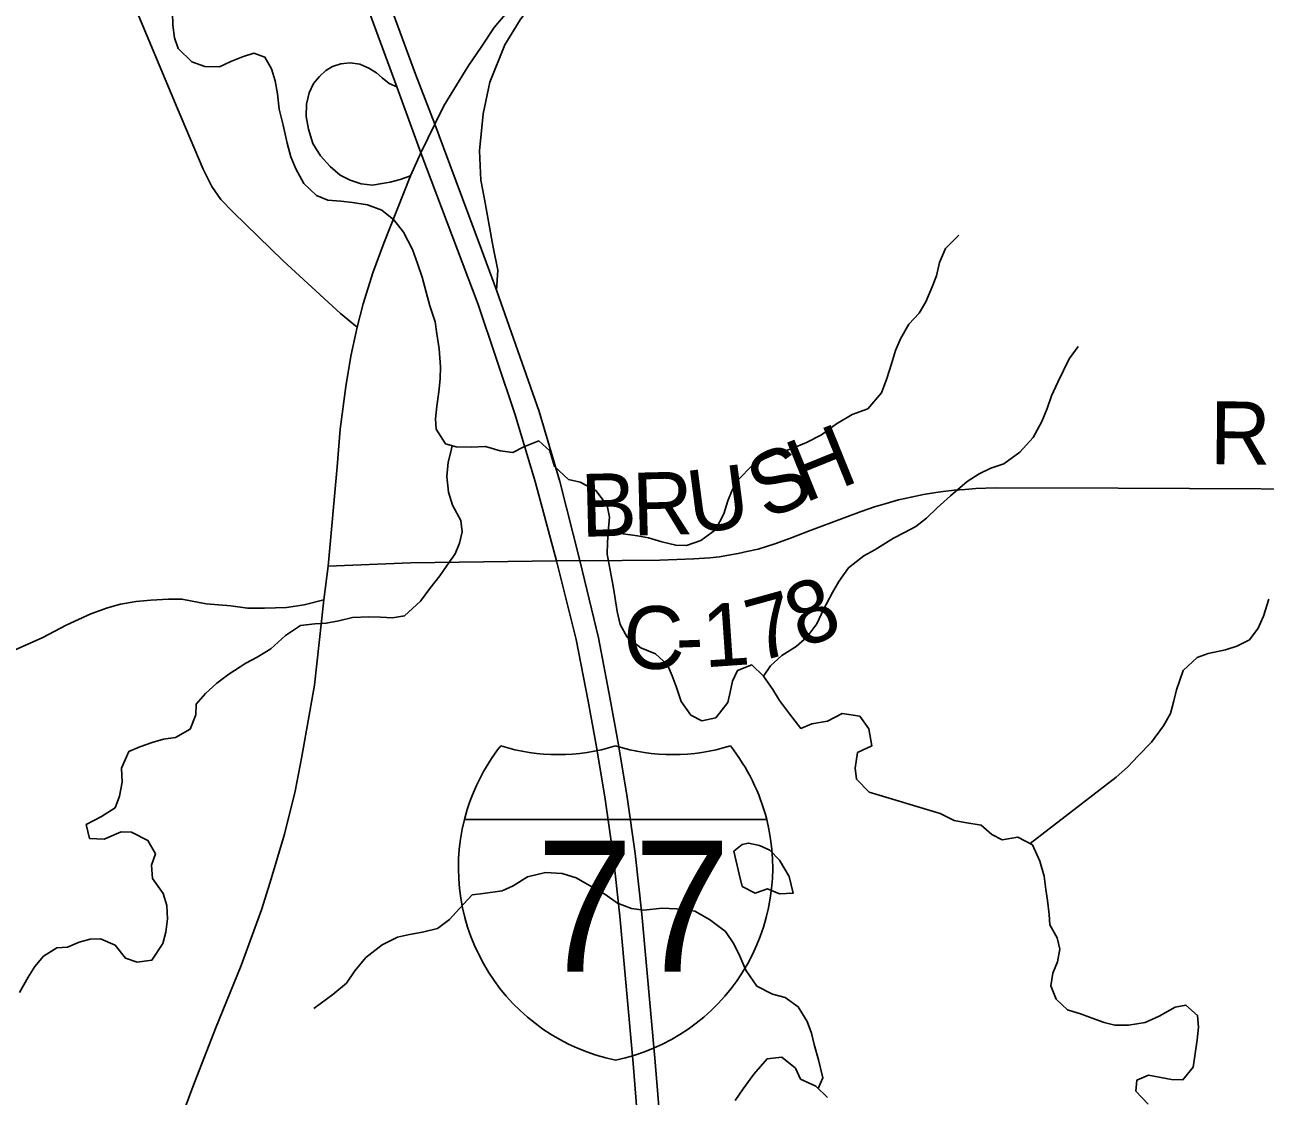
# Model space of a CAD drawing. Extents: x 0 to 34, y 0 to 22.
# Drawn here: x 5.653 to 6.774, y 18.908 to 19.877 of the extents above; entities that cross this region are included whole.
import ezdxf

# ---------------------------------------------------------------- set-up
doc = ezdxf.new("R2010")
doc.units = 0
for name, color, linetype in [('GM_X_City_Street', 7, 'Continuous'), ('GM_X_County_Road', 7, 'Continuous'), ('GM_X_County_Road_Text', 7, 'Continuous'), ('GM_X_Interstate_Location', 7, 'Continuous'), ('GM_X_Interstate_Route', 7, 'Continuous'), ('GM_X_Interstate_Shield', 7, 'Continuous'), ('GM_X_Minor_Lake', 7, 'Continuous'), ('GM_X_Minor_River', 7, 'Continuous'), ('GM_X_State_Route', 7, 'Continuous')]:
    doc.layers.add(name, color=color, linetype=linetype)

msp = doc.modelspace()

# ---------------------------------------------------------------- linework, layer by layer
at = {"layer": 'GM_X_City_Street'}
msp.add_line((5.9271, 19.3876), (6.0016, 19.3906), dxfattribs=at)
msp.add_lwpolyline([(5.644, 19.3118), (5.6691, 19.3231), (5.6903, 19.334), (5.7126, 19.3443), (5.7276, 19.3499), (5.7393, 19.3531), (5.7534, 19.3556), (5.7668, 19.3568), (5.7827, 19.3577), (5.7949, 19.3577), (5.8167, 19.3535), (5.8391, 19.3515), (5.8541, 19.3496), (5.8695, 19.3496), (5.8893, 19.3501), (5.9054, 19.3526), (5.9232, 19.357)], dxfattribs=at)
at = {"layer": 'GM_X_County_Road'}
for points in [[(5.9534, 19.6037), (5.9382, 19.6159), (5.8865, 19.6636), (5.8412, 19.7076), (5.8301, 19.7191), (5.822, 19.7309), (5.814, 19.7466), (5.7907, 19.8021), (5.7419, 19.9191), (5.7283, 19.9573), (5.7195, 19.9843), (5.7082, 20.0221)], [(5.7891, 18.8744), (5.8046, 18.9165), (5.8253, 18.9692), (5.8485, 19.0262), (5.8667, 19.0766), (5.8746, 19.1017), (5.8875, 19.1451), (5.8974, 19.184), (5.9034, 19.2153), (5.9148, 19.2798), (5.9232, 19.357), (5.9271, 19.3876), (5.9354, 19.4774), (5.9379, 19.5114), (5.943, 19.55), (5.9476, 19.5775), (5.9534, 19.6037), (5.9589, 19.6249), (5.9674, 19.6528), (5.9775, 19.6797), (6.0017, 19.7406)], [(6.159, 19.3924), (6.2269, 19.393), (6.2579, 19.3942), (6.2722, 19.3951), (6.2809, 19.3959), (6.2891, 19.3973), (6.2978, 19.3988), (6.3058, 19.4007), (6.316, 19.4029), (6.331, 19.4076), (6.3451, 19.4128), (6.3615, 19.419), (6.3936, 19.4311), (6.4092, 19.4368), (6.4212, 19.4412), (6.4317, 19.4441), (6.443, 19.4474), (6.4542, 19.45), (6.4655, 19.4524), (6.4765, 19.4541), (6.4834, 19.4551), (6.4933, 19.4561), (6.5031, 19.4569), (6.5128, 19.4577), (6.5305, 19.4583), (6.6415, 19.4581), (6.8998, 19.4568)], [(6.0016, 19.3906), (6.1336, 19.3922), (6.1546, 19.3926), (6.159, 19.3924)]]:
    msp.add_lwpolyline(points, dxfattribs=at)
at = {"layer": 'GM_X_Interstate_Route'}
for p, q in [((6.0657, 19.674), (6.0314, 19.7661)), ((6.0793, 19.6371), (6.0657, 19.674))]:
    msp.add_line(p, q, dxfattribs=at)
for points in [[(5.9892, 19.821), (5.9247, 19.9966), (5.8947, 20.0779), (5.8532, 20.1908), (5.8395, 20.2305), (5.8289, 20.2705), (5.8221, 20.3024), (5.8153, 20.3469), (5.8104, 20.3837), (5.8083, 20.45), (5.8081, 20.5587), (5.8083, 20.8248), (5.8083, 20.8307), (5.8082, 20.8456), (5.8081, 20.9)], [(6.0314, 19.7661), (6.0236, 19.7873), (6.0062, 19.8324), (5.9435, 20.003), (5.9135, 20.0843), (5.8719, 20.1972), (5.8583, 20.237), (5.8532, 20.256)], [(6.2784, 18.03), (6.2663, 18.1828), (6.2513, 18.3594), (6.2416, 18.4733), (6.2268, 18.6547), (6.2115, 18.831), (6.2029, 18.9376), (6.191, 19.071), (6.1847, 19.126), (6.1776, 19.1768), (6.1697, 19.2242), (6.1621, 19.2655), (6.1515, 19.3211), (6.1336, 19.3922), (6.1144, 19.4641), (6.096, 19.5254), (6.0628, 19.6241), (6.011, 19.7614), (5.9892, 19.821)], [(6.2231, 18.9352), (6.2228, 18.9392), (6.2109, 19.0726), (6.2046, 19.1276), (6.1975, 19.1784), (6.1896, 19.2258), (6.182, 19.2671), (6.1715, 19.3226), (6.1546, 19.3926), (6.1365, 19.4642), (6.1178, 19.5274), (6.0793, 19.6371)], [(6.2611, 18.4875), (6.2467, 18.6562), (6.2315, 18.8326), (6.2231, 18.9352)]]:
    msp.add_lwpolyline(points, dxfattribs=at)
at = {"layer": 'GM_X_Interstate_Shield'}
for p, q in [((6.0504, 19.1583), (6.3236, 19.1583)), ((6.3236, 19.1583), (6.0504, 19.1583)), ((6.3236, 19.1583), (6.0504, 19.1583))]:
    msp.add_line(p, q, dxfattribs=at)
for centre, start, end in [((6.2225, 19.1148), 141.669, 165.8066), ((6.1351, 19.3947), 253.0091, 286.9909), ((6.2389, 19.3947), 253.0091, 286.9909), ((6.1515, 19.1148), 14.1934, 38.331), ((6.2225, 19.1148), 165.8066, 258.463), ((6.1515, 19.1148), 281.537, 14.1934)]:
    msp.add_arc(centre, 0.1776, start, end, dxfattribs=at)
at = {"layer": 'GM_X_Minor_Lake'}
for points in [[(6.2987, 19.1088), (6.3015, 19.0978), (6.3133, 19.0918), (6.3243, 19.0957), (6.3353, 19.0912), (6.3475, 19.0917), (6.3439, 19.1069), (6.3354, 19.1216), (6.3266, 19.1307), (6.3171, 19.1348), (6.3072, 19.137), (6.3015, 19.1358), (6.294, 19.1296)], [(6.294, 19.1296), (6.2987, 19.1088)]]:
    msp.add_lwpolyline(points, dxfattribs=at)
at = {"layer": 'GM_X_Minor_River'}
for points in [[(5.7864, 19.8882), (5.7868, 19.8768), (5.7881, 19.8654), (5.7916, 19.8556), (5.8038, 19.8435), (5.8156, 19.8395), (5.8288, 19.8392), (5.839, 19.8438), (5.8496, 19.8481), (5.8598, 19.8516), (5.87, 19.8479), (5.8758, 19.8373), (5.8793, 19.8263), (5.8813, 19.8146), (5.8829, 19.8009), (5.8864, 19.7862), (5.89, 19.7702), (5.8935, 19.7577), (5.8978, 19.7468), (5.9051, 19.7335), (5.9165, 19.7226), (5.9268, 19.7185), (5.9385, 19.7175), (5.9491, 19.7164), (5.9628, 19.7143), (5.9757, 19.7095), (5.9864, 19.7008), (5.9952, 19.6895), (6.0033, 19.674), (6.0079, 19.6611), (6.0122, 19.649), (6.0157, 19.6354), (6.0192, 19.6229), (6.0239, 19.6085), (6.0255, 19.5975), (6.0275, 19.5842), (6.0288, 19.5679), (6.0285, 19.5569), (6.0271, 19.5451), (6.0253, 19.5322), (6.0242, 19.5208), (6.0247, 19.5113), (6.0331, 19.4981), (6.043, 19.4955), (6.0563, 19.4952), (6.0695, 19.4957), (6.0828, 19.4917), (6.0942, 19.4902), (6.104, 19.4953), (6.1176, 19.5007), (6.1275, 19.4917), (6.1318, 19.4777), (6.1444, 19.466), (6.155, 19.4634), (6.1691, 19.4559), (6.1794, 19.4424), (6.1814, 19.4318), (6.1804, 19.4185), (6.1797, 19.4086), (6.1794, 19.3983), (6.1849, 19.3695)], [(6.4974, 19.687), (6.4854, 19.6748), (6.4798, 19.6622), (6.4772, 19.65), (6.4732, 19.6401), (6.4676, 19.6267), (6.4616, 19.6164), (6.4522, 19.6064), (6.4448, 19.5931), (6.4403, 19.5824), (6.4366, 19.5706), (6.4322, 19.5572), (6.4274, 19.5443), (6.415, 19.5298)], [(6.6052, 19.5862), (6.5973, 19.5751), (6.5869, 19.5538), (6.5813, 19.5415), (6.5772, 19.5301), (6.5724, 19.5183), (6.5646, 19.5038), (6.5525, 19.4907), (6.5382, 19.48), (6.5265, 19.476), (6.5159, 19.471), (6.505, 19.4641), (6.49, 19.451), (6.4779, 19.4402), (6.4682, 19.431), (6.4584, 19.4233), (6.4482, 19.4179), (6.4384, 19.4129), (6.4214, 19.4023)], [(6.1804, 19.4188), (6.1917, 19.417), (6.2069, 19.4149), (6.2168, 19.4131), (6.2289, 19.4094), (6.2414, 19.4064), (6.2513, 19.4062), (6.2641, 19.4108), (6.2773, 19.4204), (6.2848, 19.4349), (6.2885, 19.4467), (6.2925, 19.4562), (6.2981, 19.4658), (6.3105, 19.4784), (6.3215, 19.4846), (6.332, 19.4892), (6.3468, 19.4939), (6.3596, 19.4993), (6.3732, 19.5063), (6.3867, 19.5163), (6.401, 19.5248), (6.415, 19.5298)], [(6.0393, 19.4965), (6.0385, 19.492), (6.0356, 19.4814), (6.0345, 19.4685), (6.0358, 19.4544), (6.0397, 19.4427), (6.047, 19.4287), (6.0482, 19.4185), (6.046, 19.4082), (6.0419, 19.3987), (6.0348, 19.3884), (6.0281, 19.3788), (6.0191, 19.3673), (6.0105, 19.3559), (5.9962, 19.3425), (5.9852, 19.3408), (5.9746, 19.3415), (5.964, 19.3418), (5.9492, 19.3409), (5.9368, 19.3381), (5.9254, 19.3358), (5.9152, 19.3353), (5.902, 19.3337), (5.8884, 19.3248), (5.8752, 19.3126), (5.8628, 19.3052), (5.8526, 19.2998), (5.8372, 19.2898), (5.8266, 19.2818), (5.8161, 19.2722), (5.8079, 19.2626), (5.8076, 19.2531), (5.8024, 19.2402), (5.7892, 19.2325), (5.7782, 19.2309), (5.768, 19.2281), (5.7567, 19.2242), (5.7469, 19.22), (5.7402, 19.2047), (5.7407, 19.1922), (5.7385, 19.1796), (5.7346, 19.1688)], [(6.3208, 19.2879), (6.3272, 19.2974), (6.3373, 19.3066), (6.3502, 19.3147), (6.3599, 19.3232), (6.3689, 19.3354), (6.3749, 19.3484), (6.3831, 19.3636), (6.389, 19.3735), (6.3977, 19.3861), (6.4116, 19.3969), (6.4214, 19.4023)], [(6.1849, 19.3695), (6.1865, 19.36), (6.1885, 19.3464), (6.1913, 19.3346), (6.1975, 19.3233), (6.21, 19.3135), (6.223, 19.3083), (6.234, 19.2982), (6.2383, 19.2883), (6.2418, 19.2785), (6.2464, 19.2652), (6.2552, 19.2528), (6.2651, 19.2476), (6.2776, 19.2503), (6.2885, 19.2641), (6.2907, 19.2736), (6.2928, 19.2835), (6.2973, 19.293), (6.3101, 19.2981), (6.3208, 19.2879), (6.3293, 19.2758), (6.3354, 19.266), (6.3442, 19.2539), (6.3546, 19.2407), (6.3644, 19.245), (6.3787, 19.2474), (6.3919, 19.2543), (6.4079, 19.2518), (6.4159, 19.2405), (6.4187, 19.2249), (6.4059, 19.2188), (6.4037, 19.2047), (6.4049, 19.1948), (6.4164, 19.1831)], [(6.7777, 19.3576), (6.7729, 19.3424), (6.7681, 19.3313), (6.7602, 19.321), (6.7489, 19.3152), (6.7387, 19.3117), (6.7228, 19.3085), (6.713, 19.3049), (6.7002, 19.293), (6.6943, 19.2755), (6.6917, 19.2656), (6.6888, 19.2542), (6.6824, 19.2431), (6.6716, 19.2282), (6.6595, 19.2159), (6.6498, 19.2056), (6.6396, 19.1967), (6.562, 19.1365)], [(6.5272, 19.1449), (6.5176, 19.1532), (6.5028, 19.1557), (6.4933, 19.1575), (6.4804, 19.1639), (6.4164, 19.1831)], [(5.6481, 19.002), (5.6559, 19.0157), (5.6619, 19.0253), (5.6698, 19.0348), (5.6819, 19.0422), (5.6914, 19.043), (5.702, 19.0473), (5.7118, 19.0501), (5.7213, 19.0505), (5.7346, 19.0446), (5.7438, 19.0329), (5.7545, 19.0292), (5.7678, 19.0312), (5.7775, 19.0461), (5.7804, 19.0564), (5.7818, 19.0686), (5.7813, 19.0807), (5.7778, 19.0913), (5.7682, 19.1049), (5.7674, 19.1171), (5.7711, 19.1274), (5.7641, 19.1395), (5.7493, 19.1469), (5.7398, 19.1472), (5.7246, 19.1406), (5.7114, 19.1413), (5.7082, 19.1538), (5.7222, 19.1611), (5.7346, 19.1688)], [(6.6687, 18.9009), (6.6576, 18.9126), (6.6583, 18.9225), (6.6689, 18.9271), (6.6898, 18.9232), (6.7, 18.9229), (6.7094, 18.9344), (6.713, 18.9591), (6.714, 18.9705), (6.7132, 18.9811), (6.7028, 18.9905), (6.693, 18.9885), (6.6787, 18.9804), (6.6658, 18.9746), (6.6507, 18.9722), (6.6386, 18.9724), (6.6287, 18.9746), (6.618, 18.9787), (6.6082, 18.9824), (6.5956, 18.9861), (6.5853, 18.9959), (6.5806, 19.008), (6.5824, 19.0194), (6.5865, 19.0297), (6.5887, 19.0411), (6.5863, 19.0513), (6.5798, 19.063), (6.579, 19.0725), (6.5777, 19.085), (6.5761, 19.0949), (6.5745, 19.107), (6.5706, 19.1207), (6.564, 19.1354), (6.5507, 19.1425), (6.5367, 19.1401), (6.5272, 19.1449)], [(6.3702, 18.915), (6.3744, 18.9248), (6.3704, 18.9411), (6.3665, 18.9547), (6.3641, 18.965), (6.3603, 18.9756), (6.3522, 18.9888), (6.3403, 18.9974), (6.3289, 19.0004), (6.3148, 19.0075), (6.3048, 19.0222), (6.2994, 19.0347), (6.294, 19.046), (6.2863, 19.057), (6.2721, 19.0678), (6.2588, 19.0753), (6.2485, 19.0771), (6.2292, 19.0781), (6.2125, 19.0764), (6.2015, 19.0778), (6.1889, 19.0826), (6.1774, 19.0909), (6.1614, 19.0999), (6.1515, 19.1055), (6.1386, 19.1095), (6.1238, 19.1105), (6.1075, 19.1066), (6.0943, 19.0985), (6.0844, 19.0938), (6.0674, 19.0914), (6.0572, 19.0902), (6.0459, 19.0779), (6.0369, 19.0679), (6.0259, 19.0598), (6.0123, 19.0563), (6.0006, 19.0543), (5.9899, 19.0519), (5.976, 19.0449), (5.9613, 19.0334), (5.9511, 19.0215), (5.9436, 19.0104), (5.9312, 19.0001), (5.9142, 18.9874)], [(6.2952, 18.9043), (6.3024, 18.9146), (6.3121, 18.928), (6.3241, 18.9418), (6.3374, 18.9434), (6.3496, 18.9333), (6.3543, 18.9235), (6.368, 18.9171), (6.3787, 18.907)]]:
    msp.add_lwpolyline(points, dxfattribs=at)
at = {"layer": 'GM_X_State_Route'}
for points in [[(6.0764, 19.6759), (6.0754, 19.6808), (6.0686, 19.7195), (6.0651, 19.7366), (6.0641, 19.763), (6.0672, 19.7966), (6.0733, 19.8251), (6.0869, 19.859), (6.1007, 19.8817), (6.1312, 19.9225)], [(5.9414, 19.8421), (5.9387, 19.8419), (5.9309, 19.8395), (5.9251, 19.8359), (5.9193, 19.8305), (5.9139, 19.8241), (5.9099, 19.8157), (5.9074, 19.8054), (5.9073, 19.7942), (5.9092, 19.7828), (5.9133, 19.7698), (5.9203, 19.7586), (5.929, 19.7489), (5.9379, 19.7412), (5.9469, 19.7366), (5.9569, 19.7334), (5.9672, 19.7322), (5.9759, 19.7337), (5.9832, 19.7349), (5.9922, 19.7373), (6.0017, 19.7406), (6.011, 19.7614), (6.0236, 19.7873), (6.0318, 19.8037), (6.0409, 19.8186), (6.0538, 19.8397), (6.0656, 19.8568), (6.0772, 19.8747), (6.0904, 19.8904)], [(5.9892, 19.821), (5.9823, 19.8239), (5.9759, 19.8293), (5.9709, 19.8338), (5.9639, 19.838), (5.9557, 19.8416), (5.947, 19.8426), (5.9414, 19.8421)], [(6.0793, 19.6371), (6.0807, 19.6553), (6.0764, 19.6759)], [(6.2231, 18.9352), (6.2228, 18.9392), (6.2109, 19.0726), (6.2046, 19.1276), (6.1975, 19.1784), (6.1896, 19.2258), (6.182, 19.2671), (6.1715, 19.3226), (6.1546, 19.3926), (6.1365, 19.4642), (6.1178, 19.5274), (6.0793, 19.6371)], [(6.2611, 18.4875), (6.2467, 18.6562), (6.2315, 18.8326), (6.2231, 18.9352)]]:
    msp.add_lwpolyline(points, dxfattribs=at)

# ---------------------------------------------------------------- texts
at = {"layer": 'GM_X_County_Road_Text'}
for s, height, rotation, p in [('RD', 0.05682, 359.5064, (6.7243, 19.4798)), ('H', 0.0568, 22.0463, (6.3577, 19.4443)), ('S', 0.0568, 24.8433, (6.3235, 19.4285)), ('B', 0.0568, 1.3935, (6.1561, 19.414)), ('R', 0.0568, 1.4591, (6.2028, 19.4151)), ('U', 0.0568, 7.4372, (6.2559, 19.4168)), ('8', 0.0568, 22.6596, (6.3558, 19.3123)), ('7', 0.0568, 15.4466, (6.3147, 19.3004)), ('C', 0.0568, 1.4677, (6.1949, 19.2938)), ('1', 0.0568, 3.95, (6.2675, 19.2959)), ('-', 0.0568, 1.9778, (6.2421, 19.295))]:
    msp.add_text(s, height=height, rotation=rotation, dxfattribs=at).set_placement(p)
at = {"layer": 'GM_X_Interstate_Location'}
for s in ['-', '.', ',']:
    msp.add_text(s, height=0.000189, dxfattribs=at).set_placement((6.187, 19.0828))
msp.add_text('77', height=0.000189, rotation=0, dxfattribs=at).set_placement((6.1483, 19.0436))
at = {"layer": 'GM_X_Interstate_Shield'}
msp.add_text('77', height=0.11837, dxfattribs=at).set_placement((6.1151, 19.0207))

doc.saveas('drawing.dxf')
